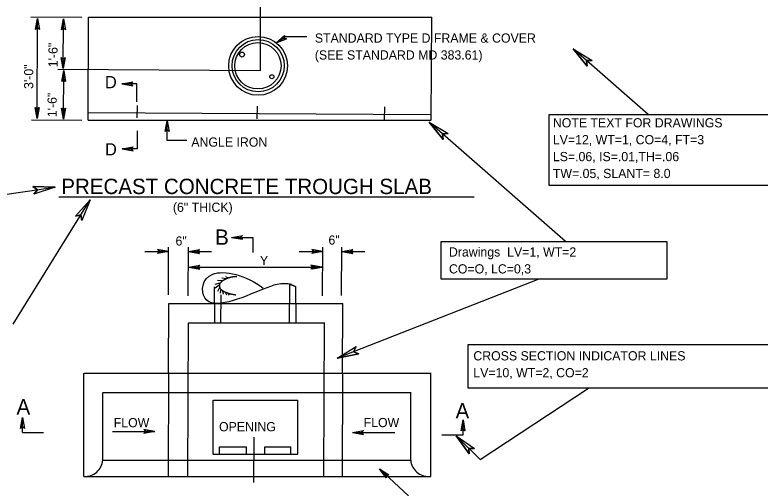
# Model space of a CAD drawing. Extents: x -0.5 to 21.6, y 4.3 to 17.8.
# Drawn here: x 2.452 to 7.307, y 12.375 to 15.456 of the extents above; entities that cross this region are included whole.
import ezdxf

# ---------------------------------------------------------------- set-up
doc = ezdxf.new("R2010")
doc.units = 0
for name, color, linetype in [('DETL-DIMS', 7, 'Continuous'), ('DETL-LINE', 7, 'Continuous'), ('DETL-NOTE', 7, 'Continuous'), ('DETL-TITL', 7, 'Continuous')]:
    doc.layers.add(name, color=color, linetype=linetype)

msp = doc.modelspace()

# ---------------------------------------------------------------- linework, layer by layer
at = {"layer": 'DETL-DIMS'}
for p, q in [((4.0522, 15.0949), (4.0522, 15.5697)), ((2.5551, 15.4426), (2.8876, 15.4406)), ((2.5998, 15.4321), (2.5868, 15.3607)), ((2.5958, 14.7807), (2.5998, 15.4321)), ((2.5998, 15.4321), (2.612, 15.3605)), ((2.7681, 15.4298), (2.7551, 15.3584)), ((2.7661, 15.108), (2.7681, 15.4298)), ((2.7681, 15.4298), (2.7803, 15.3582)), ((2.5868, 15.3607), (2.5994, 15.3741)), ((2.5994, 15.3741), (2.612, 15.3605)), ((2.7551, 15.3584), (2.7677, 15.3718)), ((2.7677, 15.3718), (2.7803, 15.3582)), ((4.1531, 15.2741), (4.2072, 15.3225)), ((4.2149, 15.3125), (4.1531, 15.2741)), ((4.1531, 15.2741), (4.2205, 15.3011)), ((4.2024, 15.3047), (4.2072, 15.3225)), ((4.2205, 15.3011), (4.2024, 15.3047)), ((4.3543, 15.3125), (4.2149, 15.3125)), ((6.0884, 15.2348), (6.1794, 15.1216)), ((6.0884, 15.2348), (6.2126, 15.1596)), ((6.5764, 14.8078), (6.0884, 15.2348)), ((2.7661, 15.108), (2.7539, 15.1796)), ((2.7665, 15.166), (2.7539, 15.1796)), ((2.7661, 15.108), (2.7791, 15.1794)), ((2.7791, 15.1794), (2.7665, 15.166)), ((6.1758, 15.1584), (6.2126, 15.1596)), ((6.1794, 15.1216), (6.1758, 15.1584)), ((2.7322, 15.103), (4.0522, 15.0949)), ((2.7699, 15.0937), (2.7568, 15.0223)), ((2.7679, 14.7766), (2.7699, 15.0937)), ((2.7699, 15.0937), (2.782, 15.0221)), ((2.7568, 15.0223), (2.7695, 15.0357)), ((2.7695, 15.0357), (2.782, 15.0221)), ((3.1479, 15.0069), (3.2194, 15.0195)), ((3.2467, 15.0069), (3.1479, 15.0069)), ((3.1479, 15.0069), (3.2194, 14.9943)), ((3.2059, 15.0069), (3.2194, 15.0195)), ((3.2194, 14.9943), (3.2059, 15.0069)), ((3.2467, 14.8895), (3.2467, 15.0069)), ((2.5958, 14.7807), (2.5836, 14.8523)), ((2.5962, 14.8387), (2.5836, 14.8523)), ((2.5958, 14.7807), (2.6088, 14.8521)), ((2.6088, 14.8521), (2.5962, 14.8387)), ((2.7679, 14.7766), (2.7558, 14.8482)), ((2.7683, 14.8346), (2.7558, 14.8482)), ((2.7679, 14.7766), (2.781, 14.848)), ((2.781, 14.848), (2.7683, 14.8346)), ((2.5591, 14.7721), (2.8879, 14.7701)), ((3.4439, 14.7673), (3.4313, 14.6958)), ((3.4439, 14.6375), (3.4439, 14.7673)), ((3.4439, 14.7673), (3.4565, 14.6958)), ((5.15, 14.7583), (5.241, 14.6451)), ((5.15, 14.7583), (5.2742, 14.6831)), ((6.0396, 13.9799), (5.15, 14.7583)), ((3.2498, 14.5836), (3.2498, 14.7011)), ((3.4313, 14.6958), (3.4439, 14.7093)), ((3.4439, 14.7093), (3.4565, 14.6958)), ((5.2374, 14.6819), (5.2742, 14.6831)), ((5.241, 14.6451), (5.2374, 14.6819)), ((3.5721, 14.6375), (3.4439, 14.6375)), ((3.151, 14.5836), (3.2225, 14.5962)), ((3.2498, 14.5836), (3.151, 14.5836)), ((3.151, 14.5836), (3.2225, 14.571)), ((3.209, 14.5836), (3.2225, 14.5962)), ((3.2225, 14.571), (3.209, 14.5836)), ((1.4601, 14.1527), (2.7134, 14.3344)), ((2.7134, 14.3344), (2.5682, 14.3388)), ((2.5682, 14.3388), (2.5986, 14.3178)), ((2.7134, 14.3344), (2.5754, 14.289)), ((2.5986, 14.3178), (2.5754, 14.289)), ((2.4408, 13.4428), (2.9424, 14.2526)), ((2.9424, 14.2526), (2.8456, 14.1444)), ((2.9424, 14.2526), (2.8886, 14.1178)), ((2.8456, 14.1444), (2.8814, 14.154)), ((2.8814, 14.154), (2.8886, 14.1178)), ((3.8637, 14.0073), (3.9352, 14.0199)), ((3.8637, 14.0073), (4.0018, 14.0073)), ((3.8637, 14.0073), (3.9352, 13.9947)), ((3.9217, 14.0073), (3.9352, 14.0199)), ((3.9352, 13.9947), (3.9217, 14.0073)), ((4.0018, 14.0073), (4.0018, 13.9411)), ((3.4513, 13.6342), (3.4527, 13.9446)), ((3.5807, 13.6263), (3.582, 13.9446)), ((4.0018, 13.9411), (4.0018, 13.9099)), ((4.4562, 13.6263), (4.4576, 13.9446)), ((4.5798, 13.6292), (4.5812, 13.9446)), ((3.2991, 13.9152), (3.4526, 13.9152)), ((3.4526, 13.9152), (3.3811, 13.9278)), ((3.3811, 13.9278), (3.3946, 13.9152)), ((3.4526, 13.9152), (3.3811, 13.9026)), ((3.3946, 13.9152), (3.3811, 13.9026)), ((3.5819, 13.9152), (3.6534, 13.9278)), ((3.5819, 13.9152), (3.732, 13.9152)), ((3.5819, 13.9152), (3.6534, 13.9026)), ((3.6399, 13.9152), (3.6534, 13.9278)), ((3.6534, 13.9026), (3.6399, 13.9152)), ((4.304, 13.9152), (4.4575, 13.9152)), ((4.4575, 13.9152), (4.386, 13.9278)), ((4.386, 13.9278), (4.3995, 13.9152)), ((4.4575, 13.9152), (4.386, 13.9026)), ((4.3995, 13.9152), (4.386, 13.9026)), ((4.5811, 13.9152), (4.6526, 13.9278)), ((4.5811, 13.9152), (4.6526, 13.9026)), ((4.5811, 13.9152), (4.7312, 13.9152)), ((4.6391, 13.9152), (4.6526, 13.9278)), ((4.6526, 13.9026), (4.6391, 13.9152)), ((3.5858, 13.8139), (3.6573, 13.8265)), ((3.5858, 13.8139), (4.4506, 13.8139)), ((3.5858, 13.8139), (3.6573, 13.8013)), ((3.6438, 13.8139), (3.6573, 13.8265)), ((3.6573, 13.8013), (3.6438, 13.8139)), ((4.4506, 13.8139), (4.3791, 13.8265)), ((4.3791, 13.8265), (4.3926, 13.8139)), ((4.4506, 13.8139), (4.3791, 13.8013)), ((4.3926, 13.8139), (4.3791, 13.8013)), ((4.3883, 13.8243), (4.4506, 13.8139)), ((4.3883, 13.8243), (4.3961, 13.8139)), ((4.3883, 13.8035), (4.4506, 13.8139)), ((4.3883, 13.8035), (4.3961, 13.8139)), ((5.8655, 13.7347), (4.5502, 13.2206)), ((4.5502, 13.2206), (4.6742, 13.2962)), ((4.6582, 13.2628), (4.6742, 13.2962)), ((4.6926, 13.2492), (4.6582, 13.2628)), ((4.5502, 13.2206), (4.6926, 13.2492)), ((5.4838, 12.5614), (6.1889, 13.0264)), ((2.5006, 12.834), (2.488, 12.7625)), ((2.5006, 12.7365), (2.5006, 12.834)), ((2.5006, 12.834), (2.5132, 12.7625)), ((5.3713, 12.8183), (5.3587, 12.7468)), ((5.3713, 12.7208), (5.3713, 12.8183)), ((5.3713, 12.8183), (5.3839, 12.7468)), ((2.488, 12.7625), (2.5006, 12.776)), ((2.5006, 12.776), (2.5132, 12.7625)), ((2.5006, 12.7365), (2.6385, 12.7365)), ((3.0878, 12.7427), (3.3634, 12.7427)), ((3.3634, 12.7427), (3.2919, 12.7553)), ((3.2919, 12.7553), (3.3054, 12.7427)), ((3.3634, 12.7427), (3.2919, 12.7301)), ((3.3054, 12.7427), (3.2919, 12.7301)), ((4.6508, 12.7365), (4.7223, 12.7491)), ((4.6508, 12.7365), (4.9265, 12.7365)), ((4.6508, 12.7365), (4.7223, 12.7239)), ((4.7088, 12.7365), (4.7223, 12.7491)), ((4.7223, 12.7239), (4.7088, 12.7365)), ((5.2334, 12.7208), (5.3713, 12.7208)), ((5.3587, 12.7468), (5.3713, 12.7603)), ((5.3713, 12.7603), (5.3839, 12.7468)), ((5.3256, 12.7141), (5.4838, 12.5614)), ((5.3256, 12.7141), (5.411, 12.5967)), ((5.3256, 12.7141), (5.446, 12.6329)), ((5.411, 12.5967), (5.4091, 12.6335)), ((5.4091, 12.6335), (5.446, 12.6329)), ((5.0149, 12.3232), (4.8264, 12.4999)), ((4.8264, 12.4999), (4.8699, 12.4418)), ((4.8264, 12.4999), (4.8872, 12.4602)), ((4.8699, 12.4418), (4.8687, 12.4602)), ((4.8687, 12.4602), (4.8872, 12.4602))]:
    msp.add_line(p, q, dxfattribs=at)
for points in [[(2.5868, 15.3607), (2.5998, 15.4321), (2.612, 15.3605), (2.5994, 15.3741)], [(2.7551, 15.3584), (2.7681, 15.4298), (2.7803, 15.3582), (2.7677, 15.3718)], [(4.2205, 15.3011), (4.1531, 15.2741), (4.2072, 15.3225), (4.2024, 15.3047)], [(6.1794, 15.1216), (6.0884, 15.2348), (6.2126, 15.1596), (6.1758, 15.1584)], [(2.7791, 15.1794), (2.7661, 15.108), (2.7539, 15.1796), (2.7665, 15.166)], [(2.7568, 15.0223), (2.7699, 15.0937), (2.782, 15.0221), (2.7695, 15.0357)], [(3.2194, 14.9943), (3.1479, 15.0069), (3.2194, 15.0195), (3.2059, 15.0069)], [(2.6088, 14.8521), (2.5958, 14.7807), (2.5836, 14.8523), (2.5962, 14.8387)], [(2.781, 14.848), (2.7679, 14.7766), (2.7558, 14.8482), (2.7683, 14.8346)], [(3.4313, 14.6958), (3.4439, 14.7673), (3.4565, 14.6958), (3.4439, 14.7093)], [(5.241, 14.6451), (5.15, 14.7583), (5.2742, 14.6831), (5.2374, 14.6819)], [(3.2225, 14.571), (3.151, 14.5836), (3.2225, 14.5962), (3.209, 14.5836)], [(2.5682, 14.3388), (2.7134, 14.3344), (2.5754, 14.289), (2.5986, 14.3178)], [(2.8456, 14.1444), (2.9424, 14.2526), (2.8886, 14.1178), (2.8814, 14.154)], [(3.9352, 13.9947), (3.8637, 14.0073), (3.9352, 14.0199), (3.9217, 14.0073)], [(3.3811, 13.9278), (3.4526, 13.9152), (3.3811, 13.9026), (3.3946, 13.9152)], [(3.6534, 13.9026), (3.5819, 13.9152), (3.6534, 13.9278), (3.6399, 13.9152)], [(4.386, 13.9278), (4.4575, 13.9152), (4.386, 13.9026), (4.3995, 13.9152)], [(4.6526, 13.9026), (4.5811, 13.9152), (4.6526, 13.9278), (4.6391, 13.9152)], [(3.6573, 13.8013), (3.5858, 13.8139), (3.6573, 13.8265), (3.6438, 13.8139)], [(4.3791, 13.8265), (4.4506, 13.8139), (4.3791, 13.8013), (4.3926, 13.8139)], [(5.4056, 13.3099), (7.4777, 13.3099), (7.4777, 13.0264), (5.4056, 13.0264)], [(4.6926, 13.2492), (4.5502, 13.2206), (4.6742, 13.2962), (4.6582, 13.2628)], [(2.488, 12.7625), (2.5006, 12.834), (2.5132, 12.7625), (2.5006, 12.776)], [(5.3587, 12.7468), (5.3713, 12.8183), (5.3839, 12.7468), (5.3713, 12.7603)], [(3.2919, 12.7553), (3.3634, 12.7427), (3.2919, 12.7301), (3.3054, 12.7427)], [(4.7223, 12.7239), (4.6508, 12.7365), (4.7223, 12.7491), (4.7088, 12.7365)], [(5.411, 12.5967), (5.3256, 12.7141), (5.446, 12.6329), (5.4091, 12.6335)], [(4.8699, 12.4418), (4.8264, 12.4999), (4.8872, 12.4602), (4.8687, 12.4602)]]:
    msp.add_lwpolyline(points, close=True, dxfattribs=at)
at = {"layer": 'DETL-LINE'}
for p, q in [((2.928, 14.7716), (2.932, 15.4408)), ((2.932, 15.4408), (5.1683, 15.4408)), ((5.1643, 14.7737), (5.1683, 15.4408)), ((3.2489, 14.7849), (3.2494, 14.867)), ((4.0308, 14.7801), (4.0313, 14.8622)), ((4.8602, 14.775), (4.8607, 14.8571)), ((2.9297, 14.8212), (5.1569, 14.8077)), ((2.928, 14.7716), (5.1643, 14.7716)), ((3.8275, 13.7363), (3.7995, 13.7426)), ((3.843, 13.7426), (3.8256, 13.7513)), ((3.7878, 13.7097), (3.7543, 13.6998)), ((3.7834, 13.6961), (3.7555, 13.6762)), ((3.8032, 13.7234), (3.7711, 13.7258)), ((4.2409, 13.4477), (4.2419, 13.7062)), ((3.7523, 13.5744), (3.7527, 13.6857)), ((3.7847, 13.6806), (3.7711, 13.6551)), ((3.7921, 13.6663), (3.7884, 13.644)), ((3.8052, 13.6576), (3.8089, 13.6371)), ((3.8218, 13.6502), (3.8293, 13.6334)), ((3.8398, 13.6445), (3.8485, 13.6315)), ((4.2818, 13.5734), (4.2823, 13.6841)), ((3.7942, 13.4497), (3.795, 13.6336)), ((3.4522, 13.1271), (3.454, 13.577)), ((3.454, 13.577), (4.5889, 13.577)), ((3.7523, 13.5744), (3.7523, 13.4517)), ((4.2818, 13.5734), (4.2812, 13.4497)), ((4.5869, 13.1236), (4.5889, 13.577)), ((3.5789, 12.4513), (3.5833, 13.4502)), ((3.5833, 13.4502), (4.4691, 13.4502)), ((4.4649, 12.4538), (4.4691, 13.4521)), ((2.9011, 12.4507), (2.9011, 13.1228)), ((2.904, 13.1228), (5.1643, 13.1228)), ((3.4522, 13.1271), (3.4492, 12.4507)), ((4.5869, 13.1236), (4.584, 12.4519)), ((5.1613, 12.4507), (5.1613, 13.1228)), ((3.0238, 12.5573), (3.0238, 12.9964)), ((3.0257, 12.9964), (5.0326, 12.9964)), ((5.0306, 12.5573), (5.0306, 12.9964)), ((3.7432, 12.5961), (3.7432, 12.9478)), ((3.7448, 12.9478), (4.2957, 12.9478)), ((4.2942, 12.5961), (4.2942, 12.9478)), ((4.0086, 12.4107), (4.0099, 12.7063)), ((3.7851, 12.5961), (3.7853, 12.6437)), ((3.7853, 12.6437), (3.9609, 12.6437)), ((3.9606, 12.5961), (3.9609, 12.6437)), ((4.0791, 12.5961), (4.0793, 12.6437)), ((4.0793, 12.6437), (4.2498, 12.6437)), ((4.2496, 12.5961), (4.2498, 12.6437)), ((3.7432, 12.5961), (4.2942, 12.5961)), ((3.0238, 12.5573), (5.0306, 12.5573)), ((2.9011, 12.4507), (5.1613, 12.4507))]:
    msp.add_line(p, q, dxfattribs=at)
msp.add_lwpolyline([(5.2291, 13.9799), (6.6982, 13.9799), (6.6982, 13.7347), (5.2291, 13.7347)], close=True, dxfattribs=at)
for centre, major_axis in [((4.0358, 15.1241), (0.1914, 0)), ((4.0364, 15.1254), (0.1702, 0)), ((4.0349, 15.1247), (0.1511, 0)), ((3.9314, 15.1978), (0.0159, 0)), ((4.1254, 15.0535), (0.0134, 0))]:
    msp.add_ellipse(centre, major_axis=major_axis, ratio=0.999935, dxfattribs=at)
for centre, major_axis, start_param, end_param in [((2.9101, 12.5643), (0.1139, 0), 4.632879, 6.222037), ((5.1444, 12.5643), (-0.1139, 0), 0.061149, 1.650306)]:
    msp.add_ellipse(centre, major_axis=major_axis, ratio=0.999935, start_param=start_param, end_param=end_param, dxfattribs=at)
msp.add_open_spline([(4.2531, 13.6997), (4.187, 13.716), (4.0846, 13.6776), (3.8323, 13.5707), (3.6584, 13.5698), (3.6713, 13.8264), (3.9573, 13.7643), (4.07, 13.6769)], degree=3, dxfattribs=at)
for points in [[(3.8981, 13.7513), (3.8944, 13.7513), (3.8827, 13.75), (3.8721, 13.7494), (3.8653, 13.7488), (3.8634, 13.7488), (3.8627, 13.7481), (3.8597, 13.7476), (3.8585, 13.7476), (3.8572, 13.7469), (3.856, 13.7469), (3.8553, 13.7463), (3.8548, 13.7463), (3.8535, 13.7457), (3.8529, 13.7457), (3.851, 13.7451), (3.8498, 13.7444), (3.8492, 13.7444), (3.8467, 13.7438), (3.8461, 13.7432), (3.8448, 13.7432), (3.8436, 13.7426), (3.843, 13.742), (3.8418, 13.742), (3.8393, 13.7407), (3.8374, 13.7401), (3.8367, 13.7394), (3.8343, 13.7388), (3.8336, 13.7388), (3.8319, 13.7383), (3.8305, 13.7376), (3.8299, 13.737), (3.8268, 13.7357), (3.8262, 13.7351), (3.825, 13.7351), (3.8237, 13.7346), (3.8231, 13.7339), (3.8225, 13.7339), (3.8188, 13.732), (3.8181, 13.7313), (3.8176, 13.7313), (3.8163, 13.7309), (3.8157, 13.7302), (3.8144, 13.7295), (3.8126, 13.7283), (3.8114, 13.7283), (3.8101, 13.7271), (3.8094, 13.7271), (3.8089, 13.7264), (3.8076, 13.7258), (3.807, 13.7252), (3.8057, 13.7252), (3.8039, 13.7234), (3.802, 13.7221), (3.8014, 13.7215), (3.8002, 13.7209), (3.7995, 13.7209), (3.7977, 13.719), (3.7964, 13.7184), (3.7958, 13.7178), (3.7946, 13.7159), (3.794, 13.7153), (3.7927, 13.7147), (3.7921, 13.7141), (3.7921, 13.7134), (3.7909, 13.7122), (3.7909, 13.7116), (3.789, 13.7097), (3.7878, 13.7072), (3.7878, 13.7066), (3.7865, 13.706), (3.7859, 13.7048), (3.7859, 13.7042), (3.7853, 13.7035), (3.7853, 13.7022), (3.7847, 13.701), (3.7841, 13.6991), (3.7841, 13.6979), (3.7847, 13.6892), (3.7847, 13.6862), (3.7853, 13.6855), (3.7853, 13.6837), (3.7859, 13.683), (3.7859, 13.6824), (3.7859, 13.6812), (3.7859, 13.6806), (3.7865, 13.6793), (3.7871, 13.6786), (3.7871, 13.6769), (3.7878, 13.6762), (3.7878, 13.6756), (3.7884, 13.6749), (3.789, 13.6738), (3.7915, 13.6712), (3.7921, 13.67), (3.7927, 13.6694), (3.7933, 13.6694)], [(4.246, 13.7005), (4.2473, 13.7005), (4.2486, 13.6998), (4.2504, 13.6998), (4.2504, 13.6991), (4.2523, 13.6991), (4.2523, 13.6985), (4.2535, 13.6985), (4.2547, 13.6979), (4.256, 13.6979), (4.2566, 13.6973), (4.2584, 13.6973), (4.2591, 13.6967), (4.2604, 13.6967), (4.2609, 13.6961), (4.2616, 13.6961), (4.2622, 13.6954), (4.2641, 13.6954), (4.2646, 13.6948), (4.2653, 13.6948), (4.2659, 13.6942), (4.2665, 13.6942), (4.2678, 13.6936), (4.2684, 13.6936), (4.2684, 13.693), (4.2696, 13.693), (4.2696, 13.6923), (4.2709, 13.6923), (4.2715, 13.6917), (4.2721, 13.6917), (4.2733, 13.6904), (4.274, 13.6904), (4.274, 13.6899), (4.2747, 13.6899), (4.2752, 13.6899), (4.2752, 13.6892), (4.2764, 13.6892), (4.2764, 13.6886), (4.2771, 13.6886), (4.2771, 13.688), (4.2784, 13.688), (4.2784, 13.6874), (4.2789, 13.6874), (4.2802, 13.6862), (4.2808, 13.6862), (4.2814, 13.6862), (4.2814, 13.6855), (4.2821, 13.6855), (4.2827, 13.6849)], [(3.7933, 13.6694), (3.7952, 13.6675), (3.7958, 13.6675), (3.7983, 13.665), (3.7995, 13.6644), (3.8008, 13.6632), (3.802, 13.6626), (3.8026, 13.6619), (3.8032, 13.6619), (3.8046, 13.6607), (3.8052, 13.6607), (3.8057, 13.6601), (3.807, 13.6595), (3.8076, 13.6589), (3.8089, 13.6582), (3.8089, 13.6576), (3.8094, 13.6576), (3.8101, 13.657), (3.8114, 13.6564), (3.8126, 13.6551), (3.8144, 13.6545), (3.8157, 13.6539), (3.8163, 13.6539), (3.8188, 13.6527), (3.82, 13.652), (3.8206, 13.652), (3.8218, 13.6514), (3.8225, 13.6508), (3.8231, 13.6508), (3.8244, 13.6502), (3.8262, 13.6502), (3.8262, 13.6496), (3.8268, 13.6496), (3.8281, 13.649), (3.8293, 13.649), (3.8299, 13.6483), (3.8305, 13.6483), (3.8319, 13.6477), (3.833, 13.6477), (3.8343, 13.6471), (3.8356, 13.6471), (3.8361, 13.6465), (3.8367, 13.6465), (3.8381, 13.6458), (3.8393, 13.6458), (3.8398, 13.6452), (3.8411, 13.6445), (3.843, 13.6445), (3.8436, 13.644), (3.8442, 13.644), (3.8448, 13.6434), (3.8467, 13.6434), (3.8479, 13.6428), (3.8485, 13.6428), (3.8492, 13.6421), (3.8504, 13.6421), (3.851, 13.6414), (3.8523, 13.6414), (3.8523, 13.6408), (3.8548, 13.6403), (3.8572, 13.6403), (3.8579, 13.6397), (3.8585, 13.6397), (3.8597, 13.6397), (3.8603, 13.6391), (3.8616, 13.6391), (3.8623, 13.6384), (3.8634, 13.6384), (3.8647, 13.6377), (3.8671, 13.6377), (3.8678, 13.6371), (3.869, 13.6371), (3.8697, 13.6371), (3.8708, 13.6366), (3.8721, 13.6366), (3.8739, 13.636), (3.8752, 13.636), (3.8777, 13.6353), (3.8808, 13.6353), (3.8814, 13.6347), (3.8832, 13.6347), (3.8852, 13.6347), (3.8864, 13.634), (3.8913, 13.634)]]:
    msp.add_spline(points, degree=3, dxfattribs=at)
at = {"layer": 'DETL-NOTE'}
msp.add_lwpolyline([(5.9329, 14.8078), (7.5815, 14.8078), (7.5815, 14.3446), (5.9329, 14.3446)], close=True, dxfattribs=at)
at = {"layer": 'DETL-TITL'}
msp.add_line((2.7389, 14.2707), (5.4429, 14.2707), dxfattribs=at)

# ---------------------------------------------------------------- texts
at = {"layer": 'DETL-DIMS'}
for s, p in [('CROSS SECTION INDICATOR LINES', (5.4384, 13.206)), ('LV=10, WT=2, CO=2 ', (5.4384, 13.096))]:
    msp.add_text(s, height=0.06, dxfattribs=at).set_placement(p)
at = {"layer": 'DETL-LINE'}
for s, p in [('Drawings  LV=1, WT=2', (5.2795, 13.8823)), ('CO=O, LC=0,3', (5.2795, 13.7723))]:
    msp.add_text(s, height=0.06, dxfattribs=at).set_placement(p)
at = {"layer": 'DETL-NOTE'}
for s, height, p in [('STANDARD TYPE D FRAME & COVER', 0.06, (4.4058, 15.2754)), ('(SEE STANDARD MD 383.61)', 0.06, (4.4058, 15.1654)), ('NOTE TEXT FOR DRAWINGS', 0.06, (5.9564, 14.7236)), ('LV=12, WT=1, CO=4, FT=3', 0.06, (5.9564, 14.6136)), ('ANGLE IRON', 0.06, (3.6009, 14.598)), ('LS=.06, IS=.01,TH=.06', 0.06, (5.9564, 14.5036)), ('TW=.05, SLANT= 8.0', 0.06, (5.9564, 14.3936)), ('(6" THICK)', 0.06, (3.481, 14.1736)), ('B', 0.1, (3.7561, 13.9588)), ('6"', 0.06, (3.4981, 13.954)), ('6"', 0.06, (4.4946, 13.9601)), ('Y', 0.06, (4.0479, 13.8265)), ('FLOW', 0.06, (3.0956, 12.7707)), ('FLOW', 0.06, (4.7237, 12.7714)), ('OPENING', 0.06, (3.7815, 12.7444))]:
    msp.add_text(s, height=height, dxfattribs=at).set_placement(p)
for s, p in [('1\'-6"', (2.7299, 15.1151)), ('3\'-0"', (2.5714, 14.974)), ('1\'-6"', (2.724, 14.7898))]:
    msp.add_text(s, height=0.06, rotation=90, dxfattribs=at).set_placement(p)
at = {"layer": 'DETL-TITL'}
for s, height, p in [('D', 0.08, (3.038, 14.9783)), ('D', 0.08, (3.0384, 14.5406)), ('PRECAST CONCRETE TROUGH SLAB', 0.1, (2.7538, 14.2893)), ('A', 0.1, (2.4622, 12.8537)), ('A', 0.1, (5.3226, 12.8278))]:
    msp.add_text(s, height=height, dxfattribs=at).set_placement(p)

doc.saveas('drawing.dxf')
